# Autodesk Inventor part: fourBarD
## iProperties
Created: 2008-10
Part Number: fourBarD
Document SubType Name: Modeling
Designer: Lochan
Density: 1 g/cm^3
Mass: 2.624 g
Surface Area: 24.9322 cm^2
Volume: 2.624 cm^3
Author: Lochan
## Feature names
1. Extrusion1
2. Extrusion2
